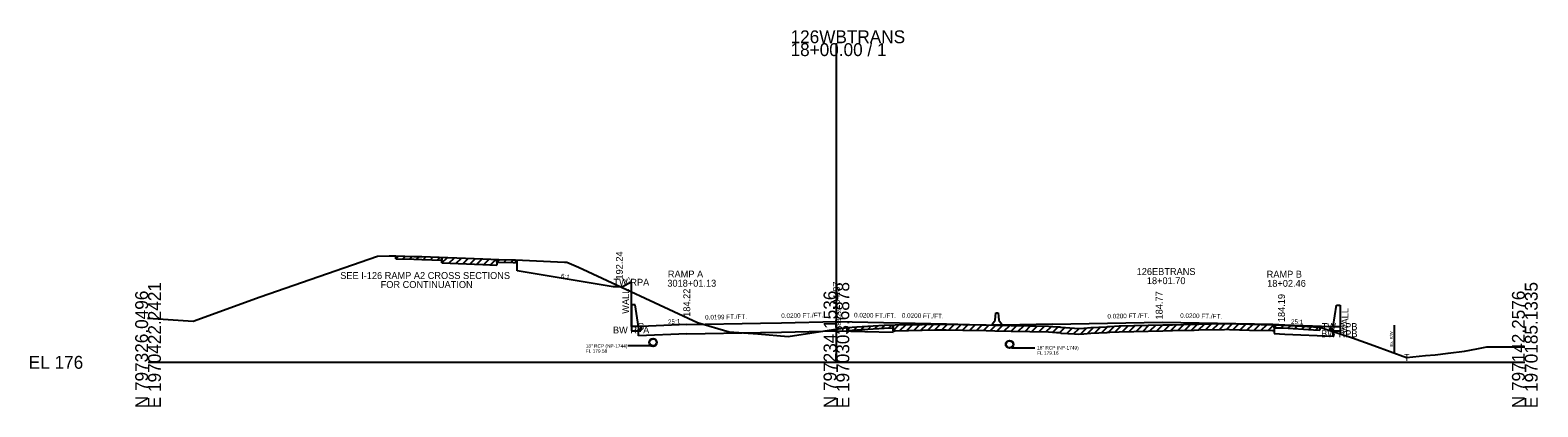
# Model space of a CAD drawing. Extents: x -6494 to 1970605, y -10 to 798140.
# Drawn here: x 974.3 to 1302.8, y 490.3 to 572.3 of the extents above; entities that cross this region are included whole.
import ezdxf

# ---------------------------------------------------------------- set-up
doc = ezdxf.new("R2010")
doc.units = 0
for name, color, linetype in [('Default', 7, 'Continuous'), ('RD_EX_SU_Misc_TxCode', 7, 'Continuous'), ('RD_GPK_XS_Cell', 7, 'Continuous'), ('RD_Sketch1', 7, 'Continuous'), ('RD_XS_Base', 7, 'Continuous'), ('RD_XS_Box', 7, 'Continuous'), ('RD_XS_EwShp', 7, 'Continuous'), ('RD_XS_ExGround', 7, 'Continuous'), ('RD_XS_ExPaveRet', 7, 'Continuous'), ('RD_XS_ExRW', 7, 'Continuous'), ('RD_XS_MedBWall', 7, 'Continuous'), ('RD_XS_Misc_Line', 7, 'Continuous'), ('RD_XS_Pave', 7, 'Continuous'), ('RD_XS_PaveOvlay', 7, 'Continuous'), ('RD_XS_PaveShd', 7, 'Continuous'), ('RD_XS_Pipe', 7, 'Continuous'), ('RD_XS_TieSlope', 7, 'Continuous'), ('RD_XS_TX_Elev_EX', 7, 'Continuous'), ('RD_XS_TX_Elev_PR', 7, 'Continuous'), ('RD_XS_TX_Misc', 7, 'Continuous'), ('RD_XS_TX_Notes', 7, 'Continuous'), ('RD_XS_TX_Profile', 7, 'Continuous'), ('RD_XS_TX_Slope', 7, 'Continuous'), ('RD_XS_TX_Station', 7, 'Continuous')]:
    doc.layers.add(name, color=color, linetype=linetype)

msp = doc.modelspace()

# ---------------------------------------------------------------- linework, layer by layer
at = {"layer": 'Default'}
for p, q in [((1184.58, 509.21), (1184.75, 510.79)), ((1184.75, 510.79), (1185.25, 510.79)), ((1185.25, 510.79), (1185.42, 509.21)), ((1184, 508.37), (1184.58, 509.21)), ((1184, 508.12), (1184, 508.37)), ((1186, 508.12), (1184, 508.12)), ((1185.42, 509.21), (1186, 508.37)), ((1186, 508.37), (1186, 508.12))]:
    msp.add_line(p, q, dxfattribs=at)
at = {"layer": 'RD_GPK_XS_Cell'}
for p, q in [((1150, 500), (1150, 569.49)), ((1000, 500), (1150, 500)), ((1150, 500), (1300, 500))]:
    msp.add_line(p, q, dxfattribs=at)
at = {"layer": 'RD_XS_Base'}
for p, q in [((1106.87, 507.24), (1107.37, 507.26)), ((1106.87, 505.76), (1106.87, 507.24)), ((1117.39, 506.18), (1106.87, 505.76)), ((1107.37, 507.26), (1107.37, 507.82)), ((1117.39, 506.18), (1133.42, 506.5)), ((1133.42, 506.5), (1138, 506.59)), ((1138, 506.59), (1150, 506.83)), ((1150, 506.83), (1162.34, 506.59)), ((1245.36, 506.24), (1247.72, 506.15)), ((1247.72, 506.15), (1258.25, 505.73)), ((1257.75, 507.23), (1257.75, 507.79)), ((1258.25, 507.21), (1257.75, 507.23)), ((1258.25, 505.73), (1258.25, 507.21))]:
    msp.add_line(p, q, dxfattribs=at)
at = {"layer": 'RD_XS_Box'}
for p, q in [((1105.37, 507.82), (1105.37, 517.44)), ((1107.37, 507.82), (1105.37, 507.82)), ((1257.75, 507.79), (1259.76, 507.79)), ((1259.76, 507.79), (1259.76, 506.21))]:
    msp.add_line(p, q, dxfattribs=at)
at = {"layer": 'RD_XS_ExGround'}
msp.add_line((999.86, 509.61), (1000, 509.6), dxfattribs=at)
msp.add_lwpolyline([(1000, 509.6), (1009.82, 508.96), (1024.42, 514.28), (1050.02, 523.13), (1052.52, 523.16), (1053.96, 523.16), (1057.93, 523.07), (1059.62, 523.04), (1072.92, 522.54), (1076.46, 522.42), (1079.59, 522.33), (1080.03, 522.32), (1090.75, 521.81), (1091.23, 521.79), (1093.76, 520.7), (1119.75, 508.64), (1126.59, 506.66), (1132.87, 506.17), (1139.49, 505.65), (1149.34, 507.12), (1150, 507.22), (1152.34, 507.57), (1154.48, 507.71), (1160.37, 508.09), (1162.78, 508.13), (1168.71, 508.24), (1171.37, 508.29), (1172.61, 508.32), (1173.9, 508.29), (1177.52, 508.23), (1182.61, 508.15), (1184.54, 508.11), (1188.08, 508.04), (1196.23, 507.87), (1197.98, 507.76), (1198.66, 507.71), (1198.93, 507.62), (1201.84, 507.42), (1202.72, 507.37), (1203.88, 507.46), (1205.42, 507.59), (1208.9, 507.72), (1209.12, 507.8), (1209.59, 507.82), (1211.63, 507.91), (1221.1, 508.13), (1223.24, 508.18), (1227.94, 508.28), (1228.95, 508.31), (1234.58, 508.43), (1235.09, 508.44), (1235.65, 508.42), (1240, 508.28), (1245.04, 508.16), (1247.33, 508.11), (1253.95, 507.72), (1255.36, 507.64), (1257.11, 507.09), (1262.48, 505.31), (1267.1, 503.66), (1274.23, 501.06), (1278.36, 501.45), (1280.46, 501.6), (1283.32, 501.98), (1286.85, 502.42), (1289.56, 502.91), (1291.69, 503.34), (1294.44, 503.34), (1300, 503.34)], dxfattribs=at)
at = {"layer": 'RD_XS_ExPaveRet'}
for p, q in [((1053.96, 522.54), (1053.96, 523.16)), ((1053.96, 522.54), (1057.93, 522.45)), ((1057.93, 522.45), (1059.62, 522.42)), ((1059.62, 522.42), (1064.05, 522.25)), ((1064.05, 521.63), (1064.05, 522.88)), ((1064.05, 522.88), (1064.05, 522.25)), ((1076.01, 522.44), (1076.01, 521.19)), ((1076.01, 521.81), (1076.01, 522.44)), ((1064.05, 521.63), (1072.92, 521.29)), ((1072.92, 521.29), (1076.01, 521.19)), ((1076.01, 521.81), (1076.46, 521.8)), ((1076.46, 521.8), (1079.59, 521.7)), ((1079.59, 521.7), (1080.03, 521.69)), ((1080.03, 522.32), (1080.03, 521.69)), ((1152.34, 506.95), (1152.34, 507.57)), ((1152.34, 506.95), (1154.48, 507.08)), ((1154.48, 507.08), (1160.37, 507.46)), ((1160.37, 507.46), (1162.34, 507.5)), ((1162.34, 506.87), (1162.34, 508.12)), ((1162.34, 508.12), (1162.34, 507.5)), ((1162.34, 506.87), (1162.78, 506.88)), ((1162.78, 506.88), (1168.71, 506.99)), ((1168.71, 506.99), (1171.37, 507.04)), ((1171.37, 507.04), (1172.61, 507.07)), ((1172.61, 507.07), (1173.9, 507.04)), ((1173.9, 507.04), (1177.52, 506.98)), ((1177.52, 506.98), (1182.61, 506.9)), ((1182.61, 506.9), (1184.54, 506.86)), ((1184.54, 506.86), (1188.08, 506.79)), ((1188.08, 506.79), (1196.23, 506.62)), ((1196.23, 506.62), (1197.98, 506.51)), ((1197.98, 506.51), (1198.66, 506.46)), ((1198.66, 506.46), (1198.93, 506.37)), ((1198.93, 506.37), (1201.84, 506.17)), ((1201.84, 506.17), (1202.72, 506.12)), ((1202.72, 506.12), (1203.88, 506.21)), ((1203.88, 506.21), (1205.42, 506.34)), ((1205.42, 506.34), (1208.9, 506.47)), ((1208.9, 506.47), (1209.12, 506.55)), ((1209.12, 506.55), (1209.59, 506.57)), ((1209.59, 506.57), (1211.63, 506.66)), ((1211.63, 506.66), (1221.1, 506.88)), ((1221.1, 506.88), (1223.24, 506.93)), ((1223.24, 506.93), (1227.94, 507.03)), ((1227.94, 507.03), (1228.95, 507.06)), ((1228.95, 507.06), (1234.58, 507.18)), ((1234.58, 507.18), (1235.09, 507.19)), ((1235.09, 507.19), (1235.65, 507.17)), ((1235.65, 507.17), (1240, 507.03)), ((1240, 507.03), (1245.04, 506.91)), ((1245.04, 506.91), (1245.36, 506.9)), ((1245.36, 508.15), (1245.36, 506.9)), ((1245.36, 507.53), (1245.36, 508.15)), ((1245.36, 507.53), (1247.33, 507.48)), ((1247.33, 507.48), (1253.95, 507.09)), ((1253.95, 507.09), (1255.36, 507.01)), ((1255.36, 507.64), (1255.36, 507.01))]:
    msp.add_line(p, q, dxfattribs=at)
at = {"layer": 'RD_XS_ExRW'}
msp.add_line((1271.5, 508.06), (1271.5, 502.06), dxfattribs=at)
at = {"layer": 'RD_XS_MedBWall'}
for p, q in [((1106.12, 512.49), (1105.37, 512.49)), ((1105.37, 512.49), (1105.37, 506.82)), ((1106.87, 507.82), (1106.12, 512.49)), ((1258.25, 507.79), (1259, 512.46)), ((1259, 512.46), (1259.75, 512.46)), ((1259.75, 512.46), (1259.75, 506.79)), ((1105.37, 506.82), (1107.37, 506.82)), ((1107.37, 507.82), (1106.87, 507.82)), ((1107.37, 506.82), (1107.37, 507.82)), ((1257.75, 506.79), (1257.75, 507.79)), ((1257.75, 507.79), (1258.25, 507.79)), ((1259.75, 506.79), (1257.75, 506.79))]:
    msp.add_line(p, q, dxfattribs=at)
at = {"layer": 'RD_XS_Misc_Line'}
for p, q in [((1053.96, 522.54), (1054.58, 523.15)), ((1055.48, 522.5), (1056.09, 523.11)), ((1056.99, 522.47), (1057.61, 523.08)), ((1058.5, 522.44), (1059.12, 523.05)), ((1060.02, 522.4), (1060.62, 523.01)), ((1061.53, 522.35), (1062.14, 522.95)), ((1063.04, 522.29), (1063.65, 522.89)), ((1064.05, 521.63), (1065.27, 522.83)), ((1065.56, 521.57), (1066.78, 522.77)), ((1067.08, 521.51), (1068.29, 522.71)), ((1068.59, 521.45), (1069.81, 522.65)), ((1070.1, 521.39), (1071.32, 522.6)), ((1071.62, 521.34), (1072.83, 522.54)), ((1073.13, 521.28), (1074.35, 522.49)), ((1074.64, 521.23), (1075.87, 522.44)), ((1076.01, 521.81), (1076.62, 522.42)), ((1077.52, 521.77), (1078.14, 522.37)), ((1079.04, 521.72), (1079.65, 522.33)), ((1152.34, 506.95), (1153.01, 507.62)), ((1153.85, 507.04), (1154.52, 507.71)), ((1155.36, 507.14), (1156.04, 507.81)), ((1156.88, 507.24), (1157.55, 507.91)), ((1158.39, 507.34), (1159.06, 508.01)), ((1159.9, 507.43), (1160.57, 508.09)), ((1161.42, 507.48), (1162.06, 508.12)), ((1162.34, 506.87), (1163.62, 508.15)), ((1163.85, 506.9), (1165.14, 508.17)), ((1165.36, 506.93), (1166.65, 508.2)), ((1166.88, 506.96), (1168.16, 508.23)), ((1168.39, 506.98), (1169.68, 508.26)), ((1169.9, 507.01), (1171.19, 508.29)), ((1171.42, 507.04), (1172.7, 508.31)), ((1172.93, 507.06), (1174.17, 508.29)), ((1174.44, 507.03), (1175.68, 508.26)), ((1175.96, 507.01), (1177.2, 508.24)), ((1177.47, 506.99), (1178.71, 508.21)), ((1178.98, 506.96), (1180.22, 508.19)), ((1180.5, 506.93), (1181.73, 508.16)), ((1182.01, 506.91), (1183.25, 508.14)), ((1183.52, 506.88), (1184.76, 508.11)), ((1185.04, 506.85), (1186.27, 508.08)), ((1186.55, 506.82), (1187.78, 508.04)), ((1188.06, 506.79), (1189.3, 508.01)), ((1189.57, 506.76), (1190.81, 507.98)), ((1191.09, 506.73), (1192.32, 507.95)), ((1192.6, 506.69), (1193.84, 507.92)), ((1194.11, 506.66), (1195.35, 507.89)), ((1195.63, 506.63), (1196.84, 507.83)), ((1197.14, 506.56), (1198.32, 507.73)), ((1198.65, 506.46), (1199.77, 507.57)), ((1200.17, 506.29), (1201.35, 507.46)), ((1201.68, 506.19), (1202.89, 507.38)), ((1203.19, 506.16), (1204.57, 507.52)), ((1204.71, 506.28), (1206.05, 507.61)), ((1206.22, 506.37), (1207.53, 507.67)), ((1207.73, 506.43), (1209.12, 507.8)), ((1209.25, 506.56), (1210.56, 507.86)), ((1210.76, 506.62), (1212.07, 507.92)), ((1212.27, 506.67), (1213.56, 507.95)), ((1213.78, 506.71), (1215.08, 507.99)), ((1215.3, 506.74), (1216.59, 508.02)), ((1216.81, 506.78), (1218.1, 508.06)), ((1218.32, 506.82), (1219.62, 508.1)), ((1219.84, 506.85), (1221.13, 508.13)), ((1221.35, 506.89), (1222.64, 508.17)), ((1222.86, 506.92), (1224.15, 508.2)), ((1224.38, 506.96), (1225.67, 508.24)), ((1225.89, 506.99), (1227.18, 508.27)), ((1227.4, 507.02), (1228.69, 508.3)), ((1228.92, 507.06), (1230.2, 508.33)), ((1230.43, 507.09), (1231.72, 508.37)), ((1231.94, 507.12), (1233.23, 508.4)), ((1233.46, 507.15), (1234.74, 508.43)), ((1234.97, 507.18), (1236.2, 508.4)), ((1236.48, 507.14), (1237.7, 508.35)), ((1237.99, 507.09), (1239.22, 508.3)), ((1239.51, 507.04), (1240.74, 508.26)), ((1241.02, 507), (1242.25, 508.23)), ((1242.53, 506.97), (1243.77, 508.19)), ((1244.05, 506.93), (1245.28, 508.16)), ((1245.36, 507.53), (1245.97, 508.14)), ((1246.87, 507.5), (1247.48, 508.1)), ((1248.38, 507.42), (1248.98, 508.01)), ((1249.9, 507.33), (1250.49, 507.92)), ((1251.41, 507.24), (1252, 507.83)), ((1252.92, 507.15), (1253.52, 507.74)), ((1254.44, 507.07), (1255.03, 507.66))]:
    msp.add_line(p, q, dxfattribs=at)
at = {"layer": 'RD_XS_Pave'}
for p, q in [((1117.39, 508.22), (1133.42, 508.54)), ((1138, 508.63), (1150, 508.87)), ((1150, 508.87), (1174, 508.39)), ((1197.07, 508.29), (1221.07, 508.77)), ((1221.07, 508.77), (1233.07, 508.53)), ((1233.07, 508.53), (1245.07, 508.29)), ((1245.07, 508.29), (1247.72, 508.19))]:
    msp.add_line(p, q, dxfattribs=at)
at = {"layer": 'RD_XS_PaveOvlay'}
for p, q in [((1162.34, 508.12), (1162.78, 508.13)), ((1162.34, 508.12), (1162.34, 506.59)), ((1162.78, 508.13), (1168.71, 508.24)), ((1168.71, 508.24), (1171.37, 508.29)), ((1171.37, 508.29), (1172.61, 508.32)), ((1172.61, 508.32), (1173.9, 508.29)), ((1173.9, 508.29), (1177.52, 508.23)), ((1177.52, 508.23), (1182.61, 508.15)), ((1182.61, 508.15), (1184.54, 508.11)), ((1184.54, 508.11), (1188.08, 508.04)), ((1188.08, 508.04), (1196.23, 507.87)), ((1196.23, 507.87), (1197.98, 507.76)), ((1197.98, 507.76), (1198.66, 507.71)), ((1198.66, 507.71), (1198.93, 507.62)), ((1198.93, 507.62), (1201.84, 507.42)), ((1201.84, 507.42), (1202.72, 507.37)), ((1202.72, 507.37), (1203.88, 507.46)), ((1203.88, 507.46), (1205.42, 507.59)), ((1205.42, 507.59), (1208.9, 507.72)), ((1208.9, 507.72), (1209.12, 507.8)), ((1209.12, 507.8), (1209.59, 507.82)), ((1209.59, 507.82), (1211.63, 507.91)), ((1211.63, 507.91), (1221.1, 508.13)), ((1221.1, 508.13), (1223.24, 508.18)), ((1223.24, 508.18), (1227.94, 508.28)), ((1227.94, 508.28), (1228.95, 508.31)), ((1228.95, 508.31), (1234.58, 508.43)), ((1234.58, 508.43), (1235.09, 508.44)), ((1235.09, 508.44), (1235.65, 508.42)), ((1235.65, 508.42), (1240, 508.28)), ((1240, 508.28), (1245.04, 508.16)), ((1245.04, 508.16), (1245.36, 508.15)), ((1245.36, 508.15), (1245.36, 506.24))]:
    msp.add_line(p, q, dxfattribs=at)
at = {"layer": 'RD_XS_PaveShd'}
for p, q in [((1117.39, 508.22), (1107.37, 507.82)), ((1133.42, 508.54), (1138, 508.63)), ((1174, 508.39), (1184, 508.12)), ((1186.42, 508.07), (1184, 508.12)), ((1197.07, 508.29), (1186.42, 508.07)), ((1247.72, 508.19), (1257.75, 507.79))]:
    msp.add_line(p, q, dxfattribs=at)
at = {"layer": 'RD_XS_Pipe'}
for p, q in [((1109.53, 503.58), (1104.53, 503.58)), ((1188.23, 503.16), (1193.23, 503.16))]:
    msp.add_line(p, q, dxfattribs=at)
for centre, radius in [((1110.03, 504.33), 0.85), ((1110.03, 504.33), 0.75), ((1187.73, 503.91), 0.85), ((1187.73, 503.91), 0.75)]:
    msp.add_circle(centre, radius, dxfattribs=at)
at = {"layer": 'RD_XS_TieSlope'}
for p, q in [((1080.46, 519.93), (1080.46, 522.3)), ((1101.37, 516.44), (1080.46, 519.93)), ((1103.37, 516.44), (1101.37, 516.44)), ((1105.37, 517.44), (1103.37, 516.44))]:
    msp.add_line(p, q, dxfattribs=at)

# ---------------------------------------------------------------- texts
at = {"layer": 'RD_EX_SU_Misc_TxCode'}
msp.add_text('G', height=1.5, dxfattribs=at).set_placement((1106.62, 507.07))
at = {"layer": 'RD_GPK_XS_Cell'}
for s, p in [('126WBTRANS', (1140, 569.49)), ('18+00.00 / 1', (1140, 566.69)), ('EL 176', (974, 498.6))]:
    msp.add_text(s, height=2.8, dxfattribs=at).set_placement(p)
for s, p in [('E 1970422.2421', (1002.8, 490)), ('E 1970303.6878', (1152.8, 490)), ('E 1970185.1335', (1302.8, 490)), ('N 797326.0496', (1000, 490)), ('N 797234.1536', (1150, 490)), ('N 797142.2576', (1300, 490))]:
    msp.add_text(s, height=2.8, rotation=90, dxfattribs=at).set_placement(p)
at = {"layer": 'RD_Sketch1'}
msp.add_text('T', height=1.5, dxfattribs=at).set_placement((1273.68, 500.31))
at = {"layer": 'RD_XS_EwShp'}
for s, p in [('TW RPA', (1101.41, 516.69)), ('BW RPA', (1101.3, 506.28)), ('TW RPB', (1255.73, 507.04)), ('BW RPB', (1255.63, 505.46))]:
    msp.add_text(s, height=1.5, dxfattribs=at).set_placement(p)
at = {"layer": 'RD_XS_ExRW'}
msp.add_text('Ex. R/W ', height=0.65, rotation=90, dxfattribs=at).set_placement((1271.25, 503.44))
at = {"layer": 'RD_XS_Pipe'}
for s, p in [('18" RCP (NP-1744)', (1095.38, 503.2)), ('FL 179.58', (1095.38, 502.08)), ('18" RCP (NP-1749)', (1193.73, 502.79)), ('FL 179.16', (1193.73, 501.66))]:
    msp.add_text(s, height=0.75, dxfattribs=at).set_placement(p)
at = {"layer": 'RD_XS_TX_Elev_EX'}
msp.add_text('183.22', height=1, rotation=90, dxfattribs=at).set_placement((1151, 507.22))
at = {"layer": 'RD_XS_TX_Elev_PR'}
for s, p in [('184.22', (1118.14, 509.9)), ('184.87', (1150.75, 511.45)), (' 184.77', (1221.07, 508.77)), (' 184.19', (1247.72, 508.19))]:
    msp.add_text(s, height=1.5, rotation=90, dxfattribs=at).set_placement(p)
at = {"layer": 'RD_XS_TX_Misc'}
msp.add_text('192.24', height=1.5, rotation=90, dxfattribs=at).set_placement((1103.45, 518.02))
at = {"layer": 'RD_XS_TX_Notes'}
for s, p in [('SEE I-126 RAMP A2 CROSS SECTIONS', (1041.87, 518.15)), ('FOR CONTINUATION', (1050.68, 516.19))]:
    msp.add_text(s, height=1.5, dxfattribs=at).set_placement(p)
for p in [(1104.82, 510.57), (1261.57, 506.36)]:
    msp.add_text('WALL', height=1.5, rotation=90, dxfattribs=at).set_placement(p)
at = {"layer": 'RD_XS_TX_Profile'}
msp.add_text('25:1', height=1, rotation=357.7094, dxfattribs=at).set_placement((1249.03, 508.38))
at = {"layer": 'RD_XS_TX_Slope'}
for s, rotation, p in [('6:1', 350.5377, (1089.9, 518.35)), ('2:1', 26.5651, (1103.77, 516.96)), ('25:1', 2.2865, (1113.32, 508.31)), ('0.0199 FT./FT.', 1.1382, (1121.39, 509.3)), ('0.0200 FT./FT.', 1.1458, (1137.98, 509.63)), ('0.0200 FT./FT.', 358.8542, (1153.83, 509.8)), ('0.0200 FT./FT.', 358.8542, (1164.24, 509.73)), ('0.0200 FT./FT.', 1.1458, (1209.05, 509.53)), ('0.0200 FT./FT.', 358.8543, (1224.9, 509.69))]:
    msp.add_text(s, height=1, rotation=rotation, dxfattribs=at).set_placement(p)
at = {"layer": 'RD_XS_TX_Station'}
for s, p in [('RAMP A', (1113.27, 518.47)), ('126EBTRANS', (1215.42, 519.02)), ('RAMP B', (1243.75, 518.44)), ('3018+01.13', (1113.15, 516.47)), ('18+01.70', (1217.64, 517.02)), ('18+02.46', (1243.86, 516.44))]:
    msp.add_text(s, height=1.5, dxfattribs=at).set_placement(p)

doc.saveas('drawing.dxf')
